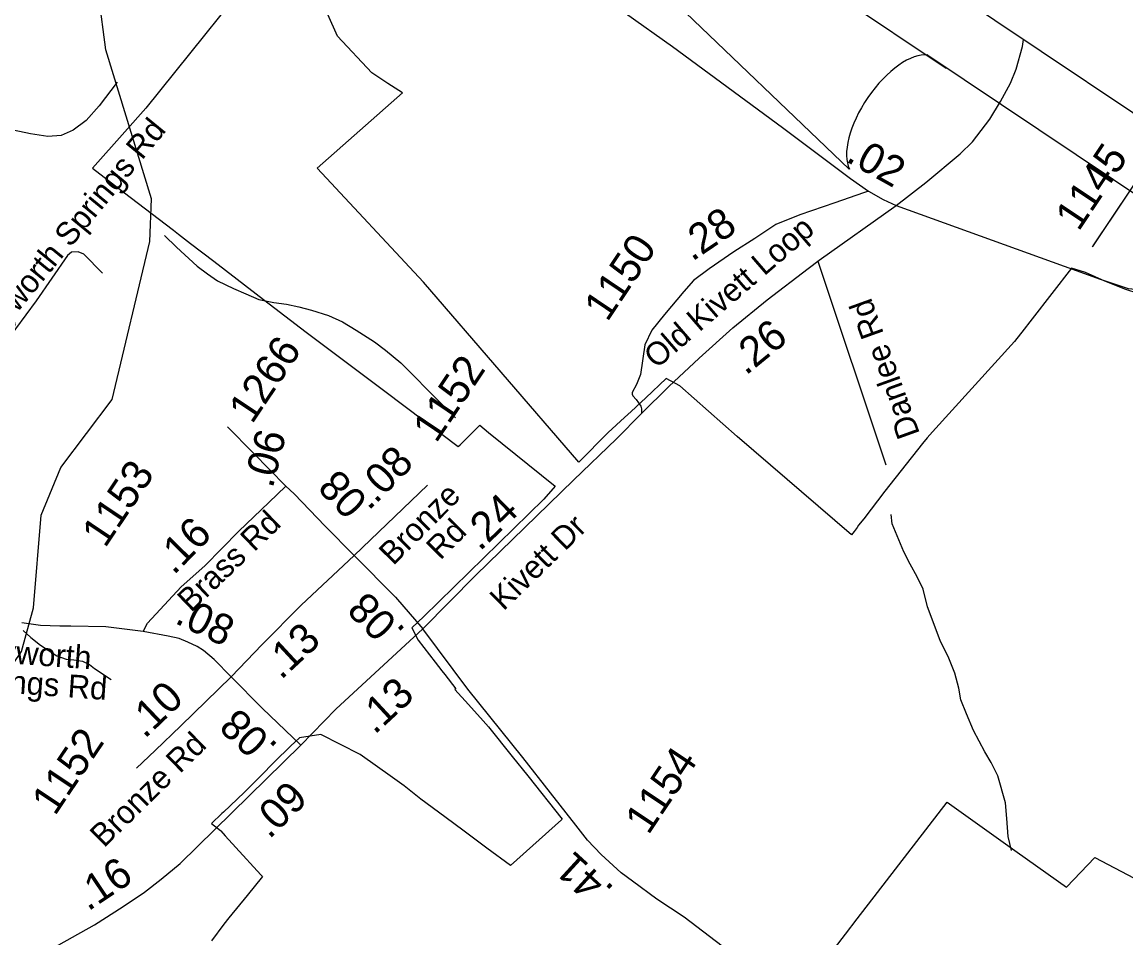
# Model space of a CAD drawing. Extents: x 1715610 to 1720914, y 798298 to 802505.
# Drawn here: x 1715932.8 to 1716031.7, y 799765.7 to 799847.8 of the extents above; entities that cross this region are included whole.
import ezdxf

# ---------------------------------------------------------------- set-up
doc = ezdxf.new("R2010")
doc.units = 0
for name, color, linetype in [('Default', 7, 'Continuous'), ('Prop DSN Text', 7, 'Continuous'), ('Prop North Arrow for Plan Sheets CELL', 7, 'Continuous')]:
    doc.layers.add(name, color=color, linetype=linetype)

msp = doc.modelspace()

# ---------------------------------------------------------------- linework, layer by layer
at = {"layer": 'Default'}
for p, q in [((1716004.107, 799826.397), (1716010.203, 799808.132)), ((1715962.545, 799800.004), (1715969.133, 799806.303))]:
    msp.add_line(p, q, dxfattribs=at)
for points in [[(1715913.865, 799783.456), (1715926.835, 799784.693), (1715929.284, 799786.328), (1715932.753, 799791.412), (1715933.821, 799795.307), (1715934.494, 799803.62), (1715936.271, 799807.905), (1715940.869, 799813.983), (1715944.236, 799828.141), (1715944.399, 799831.987), (1715940.311, 799845.322), (1715939.674, 799850.143), (1715940.195, 799853.75), (1715941.312, 799854.725), (1715943.603, 799854.265), (1715956.425, 799858.901), (1715957.776, 799859.961), (1715959.574, 799863.781), (1715959.922, 799867.267), (1715958.277, 799874.754), (1715959.996, 799882.819), (1715961.653, 799887.001)], [(1715908.697, 799873.648), (1715909.928, 799873.704), (1715920.861, 799873.543), (1715922.854, 799873.496), (1715923.734, 799873.475), (1715928.536, 799873.361), (1715933.353, 799873.131), (1715936.194, 799872.898), (1715938.663, 799872.403), (1715942.933, 799871.337), (1715946.16, 799870.365), (1715954.607, 799867.939), (1715958.8, 799866.637), (1715962.259, 799865.247), (1715963.761, 799864.692), (1715964.59, 799864.335), (1715966.206, 799863.587), (1715970.392, 799860.667), (1715982.657, 799851.643), (1715991.072, 799845.641), (1716000.954, 799838.366), (1716007.032, 799833.787), (1716008.634, 799832.651)], [(1715955.729, 799854.898), (1715943.869, 799840.108), (1715941.991, 799837.985), (1715939.098, 799834.723), (1715941.848, 799832.615), (1715946.356, 799829.159), (1715946.81, 799828.813), (1715947.89, 799827.982), (1715949.986, 799826.376), (1715954.825, 799822.666), (1715954.947, 799822.572), (1715958.261, 799820.03), (1715965.297, 799814.728), (1715968.833, 799812.07), (1715971.886, 799809.769), (1715972.041, 799809.923), (1715973.825, 799811.683), (1715974.597, 799811.042), (1715980.579, 799806.231), (1715979.545, 799805.058), (1715968.808, 799794.539), (1715967.736, 799793.522)], [(1715955.729, 799854.898), (1715943.869, 799840.108), (1715941.991, 799837.985), (1715939.098, 799834.723), (1715941.848, 799832.615), (1715946.356, 799829.159), (1715946.81, 799828.813), (1715947.89, 799827.982), (1715949.986, 799826.376), (1715954.825, 799822.666), (1715954.947, 799822.572), (1715958.261, 799820.03), (1715965.297, 799814.728), (1715968.833, 799812.07), (1715971.886, 799809.769), (1715972.041, 799809.923), (1715973.825, 799811.683), (1715974.597, 799811.042), (1715980.579, 799806.231), (1715979.545, 799805.058), (1715968.808, 799794.539), (1715967.736, 799793.522)], [(1716033.911, 799823.128), (1716031.716, 799823.864), (1716029.825, 799824.606), (1716028.093, 799825.379), (1716026.847, 799825.749), (1716023.302, 799821.215), (1716023.102, 799820.96), (1716022.588, 799820.303), (1716021.723, 799819.2), (1716014.38, 799811.081), (1716013.908, 799810.56), (1716013.473, 799810.036), (1716010.109, 799805.761), (1716008.214, 799803.28), (1716007.746, 799802.71), (1716007.624, 799802.504), (1716007.353, 799802.155), (1716007.121, 799801.856), (1715996.875, 799810.663), (1715991.726, 799815.222), (1715990.512, 799815.861), (1715988.704, 799814.127), (1715987.38, 799812.916), (1715986.79, 799812.375), (1715985.325, 799811.03), (1715982.683, 799808.358), (1715968.76, 799824.515), (1715959.239, 799834.715), (1715966.88, 799841.47), (1715965.579, 799842.321), (1715964.135, 799843.265), (1715961.045, 799846.573), (1715959.438, 799850.204)], [(1716033.911, 799823.128), (1716031.716, 799823.864), (1716029.825, 799824.606), (1716028.093, 799825.379), (1716026.847, 799825.749), (1716023.302, 799821.215), (1716023.102, 799820.96), (1716022.588, 799820.303), (1716021.723, 799819.2), (1716014.38, 799811.081), (1716013.908, 799810.56), (1716013.473, 799810.036), (1716010.109, 799805.761), (1716008.214, 799803.28), (1716007.746, 799802.71), (1716007.624, 799802.504), (1716007.353, 799802.155), (1716007.121, 799801.856), (1715996.875, 799810.663), (1715991.726, 799815.222), (1715990.512, 799815.861), (1715988.704, 799814.127), (1715987.38, 799812.916), (1715986.79, 799812.375), (1715985.325, 799811.03), (1715982.683, 799808.358), (1715968.76, 799824.515), (1715959.239, 799834.715), (1715966.88, 799841.47), (1715965.579, 799842.321), (1715964.135, 799843.265), (1715961.045, 799846.573), (1715959.438, 799850.204)], [(1716011.114, 799831.388), (1716013.774, 799833.456), (1716016.873, 799836.024), (1716017.964, 799837.092), (1716019.534, 799839.126), (1716020.487, 799840.705), (1716021.372, 799842.339), (1716021.885, 799843.606), (1716022.433, 799845.644), (1716022.542, 799846.246)], [(1715941.3, 799842.443), (1715939.695, 799840.324), (1715938.536, 799839.013), (1715937.356, 799838.134), (1715936.288, 799837.651), (1715935.115, 799837.556), (1715933.538, 799837.791), (1715931.419, 799838.238), (1715929.949, 799838.556), (1715928.372, 799838.791), (1715927.298, 799838.839), (1715926.235, 799838.826), (1715925.099, 799838.706), (1715924.057, 799838.26), (1715922.794, 799837.646), (1715920.511, 799836.464), (1715919.063, 799835.501), (1715918.128, 799834.828), (1715916.642, 799833.73), (1715915.513, 799833.079), (1715914.833, 799832.703)], [(1716008.634, 799832.651), (1716008.193, 799832.528), (1716005.615, 799831.608), (1716002.487, 799830.529), (1716000.356, 799829.689), (1715998.467, 799828.426), (1715996.589, 799827.215), (1715994.37, 799825.71), (1715992.976, 799824.669), (1715992.105, 799823.671), (1715990.357, 799821.621), (1715989.236, 799820.196), (1715988.607, 799818.881), (1715988.221, 799816.243), (1715987.849, 799815.343), (1715987.481, 799814.606), (1715987.467, 799814.473), (1715987.514, 799814.312), (1715987.817, 799813.983), (1715988.245, 799813.404), (1715988.306, 799813.158), (1715988.292, 799812.725)], [(1716008.634, 799832.651), (1716009.959, 799831.911), (1716011.114, 799831.388)], [(1715988.292, 799812.725), (1715990.755, 799815.154), (1715993.468, 799817.708), (1715996.485, 799820.404), (1715999.575, 799822.927), (1716003.228, 799825.73), (1716004.219, 799826.492), (1716011.114, 799831.388)], [(1716011.114, 799831.388), (1716029.398, 799824.782), (1716031.908, 799823.95), (1716033.862, 799823.761), (1716035.469, 799823.681), (1716047.398, 799823.718), (1716050.918, 799823.558), (1716053.263, 799823.614), (1716056.007, 799823.848)], [(1715945.548, 799828.684), (1715946.625, 799827.636), (1715948.477, 799825.951), (1715949.42, 799825.25), (1715950.319, 799824.638), (1715951.735, 799823.932), (1715952.83, 799823.451), (1715954.019, 799822.955), (1715955.355, 799822.673), (1715956.476, 799822.54), (1715957.582, 799822.309), (1715958.739, 799821.997), (1715960.266, 799821.533), (1715961.503, 799820.952), (1715962.737, 799820.212), (1715964.379, 799819.145), (1715965.361, 799818.424), (1715966.736, 799817.273), (1715970.364, 799813.637), (1715971.638, 799812.339)], [(1715939.996, 799825.319), (1715938.317, 799827.019), (1715937.804, 799827.218), (1715937.207, 799827.186), (1715936.872, 799826.9), (1715934.066, 799822.823), (1715931.265, 799819.078), (1715930.184, 799817.995), (1715929.118, 799817.053), (1715928.229, 799816.582)], [(1715968.702, 799793.445), (1715973.449, 799798.247), (1715982.221, 799806.744), (1715986.076, 799810.473), (1715988.292, 799812.725)], [(1715956.427, 799806.215), (1715953.511, 799809.194), (1715951.215, 799811.543)], [(1715943.63, 799793.205), (1715944.032, 799793.947), (1715947.058, 799797.185), (1715949.18, 799799.091), (1715952.224, 799802.194), (1715954.905, 799804.754), (1715956.427, 799806.215)], [(1715956.427, 799806.215), (1715957.178, 799805.531), (1715959.959, 799802.642), (1715962.545, 799800.004)], [(1716021.455, 799773.569), (1716021.156, 799774.827), (1716021.041, 799776.434), (1716020.937, 799777.823), (1716020.227, 799780.257), (1716019.626, 799781.459), (1716019.068, 799782.417), (1716018.051, 799784.321), (1716017.431, 799785.804), (1716016.913, 799787.053), (1716016.744, 799788.116), (1716016.396, 799789.46), (1716015.834, 799790.797), (1716015.067, 799792.373), (1716013.931, 799795.414), (1716013.537, 799796.998), (1716013.018, 799798.091), (1716012.367, 799799.219), (1716011.812, 799800.337), (1716010.78, 799802.836), (1716010.679, 799803.692)], [(1715951.53, 799789.119), (1715954.307, 799792.031), (1715957.812, 799795.551), (1715962.545, 799800.004)], [(1715962.545, 799800.004), (1715966.263, 799796.257), (1715968.702, 799793.445)], [(1715943.63, 799793.205), (1715940.312, 799793.621), (1715937.148, 799793.669), (1715936.184, 799793.668), (1715934.449, 799793.742), (1715932.777, 799793.98)], [(1715932.902, 799793.276), (1715933.583, 799792.654), (1715934.431, 799791.968), (1715935.894, 799791.022), (1715936.734, 799790.711), (1715937.435, 799790.656), (1715938.204, 799790.548), (1715938.828, 799790.228), (1715939.271, 799789.872), (1715940.768, 799788.902)], [(1715951.53, 799789.119), (1715950.017, 799790.679), (1715949.053, 799791.497), (1715948.494, 799791.835), (1715947.659, 799792.24), (1715946.883, 799792.556), (1715945.897, 799792.788), (1715943.63, 799793.205)], [(1715967.736, 799793.522), (1715968.276, 799792.425), (1715969.82, 799790.439), (1715970.411, 799789.68), (1715970.668, 799789.351), (1715971.677, 799788.051), (1715971.572, 799787.984), (1715972.793, 799786.65), (1715974.128, 799785.187), (1715974.606, 799784.661), (1715976.726, 799781.999), (1715978.11, 799780.261), (1715981.207, 799776.373), (1715981.129, 799776.304), (1715976.57, 799772.217), (1715974.449, 799773.784), (1715972.407, 799775.291), (1715970.669, 799776.572), (1715968.515, 799778.164), (1715967.022, 799779.37), (1715965.974, 799780.117), (1715963.105, 799782.162), (1715959.567, 799783.961), (1715957.65, 799783.653), (1715956.839, 799782.92), (1715955.419, 799781.499), (1715954.145, 799780.212), (1715952.703, 799778.76), (1715950.834, 799777.004), (1715950.694, 799776.872), (1715949.754, 799775.98), (1715950.574, 799775.352), (1715950.606, 799775.318), (1715950.989, 799774.888), (1715951.952, 799773.835), (1715954.182, 799771.394), (1715954.331, 799771.231), (1715952.96, 799769.539), (1715951.326, 799767.521), (1715950.864, 799766.95), (1715949.77, 799765.474)], [(1715967.736, 799793.522), (1715968.276, 799792.425), (1715969.82, 799790.439), (1715970.411, 799789.68), (1715970.668, 799789.351), (1715971.677, 799788.051), (1715971.572, 799787.984), (1715972.793, 799786.65), (1715974.128, 799785.187), (1715974.606, 799784.661), (1715976.726, 799781.999), (1715978.11, 799780.261), (1715981.207, 799776.373), (1715981.129, 799776.304), (1715976.57, 799772.217), (1715974.449, 799773.784), (1715972.407, 799775.291), (1715970.669, 799776.572), (1715968.515, 799778.164), (1715967.022, 799779.37), (1715965.974, 799780.117), (1715963.105, 799782.162), (1715959.567, 799783.961), (1715957.65, 799783.653), (1715956.839, 799782.92), (1715955.419, 799781.499), (1715954.145, 799780.212), (1715952.703, 799778.76), (1715950.834, 799777.004), (1715950.694, 799776.872), (1715949.754, 799775.98), (1715950.574, 799775.352), (1715950.606, 799775.318), (1715950.989, 799774.888), (1715951.952, 799773.835), (1715954.182, 799771.394), (1715954.331, 799771.231), (1715952.96, 799769.539), (1715951.326, 799767.521), (1715950.864, 799766.95), (1715949.77, 799765.474)], [(1715957.762, 799783.015), (1715960.904, 799786.222), (1715968.702, 799793.445)], [(1715999.432, 799761.987), (1715992.134, 799767.58), (1715989.691, 799769.214), (1715987.49, 799770.8), (1715986.473, 799771.562), (1715984.679, 799773.204), (1715983.47, 799774.479), (1715982.404, 799775.822), (1715980.138, 799778.724), (1715977.67, 799781.9), (1715972.737, 799788.033), (1715968.702, 799793.445)], [(1715943.038, 799780.956), (1715944.718, 799782.532), (1715947.014, 799784.736), (1715951.53, 799789.119)], [(1715957.762, 799783.015), (1715954.302, 799786.31), (1715951.53, 799789.119)], [(1715935.353, 799764.685), (1715939.274, 799766.904), (1715941.846, 799768.533), (1715943.771, 799769.821), (1715945.257, 799770.984), (1715946.967, 799772.383), (1715957.762, 799783.015)], [(1716002.347, 799760.535), (1716006.596, 799766.073), (1716007.642, 799767.434), (1716009.45, 799769.784), (1716015.691, 799777.891)], [(1716002.347, 799760.535), (1716006.596, 799766.073), (1716007.642, 799767.434), (1716009.45, 799769.784), (1716015.691, 799777.891)], [(1716015.691, 799777.891), (1716021.962, 799773.422), (1716026.399, 799770.262)], [(1716015.691, 799777.891), (1716021.962, 799773.422), (1716026.399, 799770.262)], [(1716026.399, 799770.262), (1716028.92, 799772.926), (1716040.648, 799766.765)], [(1716026.399, 799770.262), (1716028.92, 799772.926), (1716040.648, 799766.765)]]:
    msp.add_lwpolyline(points, dxfattribs=at)
at = {"layer": 'Prop DSN Text'}
msp.add_lwpolyline([(1715972.317, 799278.019), (1716250.513, 799693.662), (1715888.228, 799936.145), (1715610.032, 799520.501)], close=True, dxfattribs=at)
at = {"layer": 'Prop North Arrow for Plan Sheets CELL'}
for p, q in [((1716006.917, 799834.63), (1715955.981, 799883.523)), ((1715956.023, 799883.585), (1716015.608, 799843.704)), ((1716046.522, 799823.013), (1716013.863, 799844.872)), ((1716015.608, 799843.704), (1716013.925, 799844.83)), ((1716028.767, 799827.767), (1716035.442, 799837.739)), ((1716031.687, 799832.13), (1716028.725, 799827.705)), ((1716028.725, 799827.705), (1716028.683, 799827.642))]:
    msp.add_line(p, q, dxfattribs=at)
msp.add_ellipse((1716010.986, 799839.373), major_axis=(3.567, 5.248), ratio=0.461098, start_param=0.216388, end_param=2.908219, dxfattribs=at)

# ---------------------------------------------------------------- texts
at = {"layer": 'Default'}
for s, height, rotation, p in [('Hayworth Springs Rd', 2.06625, 50.67435, (1715929.236, 799817.92)), ('.02', 2.7188, 330.80515, (1716006.518, 799835.387)), ('1145', 2.7188, 56.20506, (1716027.474, 799828.985)), ('.28', 2.7188, 34.12786, (1715992.838, 799826.314)), ('Old Kivett Loop', 2.06625, 40.81056, (1715989.645, 799816.678)), ('1150', 2.7188, 56.20506, (1715985.241, 799820.877)), ('Danlee Rd', 2.0663, 109.85489, (1716013.276, 799810.925)), ('.26', 2.7188, 39.23081, (1715997.65, 799816.09)), ('1266', 2.7188, 56.20506, (1715953.403, 799811.716)), ('1152', 2.7188, 56.20506, (1715969.904, 799810.009)), ('.06', 2.7188, 75.87353, (1715955.25, 799805.963)), ('.08', 2.7188, 45.61569, (1715964.485, 799804.577)), ('1153', 2.7188, 56.20506, (1715940.236, 799800.609)), ('.08', 2.7188, 133.90369, (1715964.605, 799804.258)), ('Bronze', 2.0663, 45.12863, (1715966.049, 799799.031)), ('.24', 2.7188, 44.08762, (1715973.821, 799800.323)), ('Brass Rd', 2.0663, 43.88272, (1715947.936, 799794.843)), ('.16', 2.7188, 45.54997, (1715946.39, 799798.188)), (' Rd', 2.0663, 45.12863, (1715969.737, 799798.974)), ('Kivett Dr', 2.0663, 44.36084, (1715975.946, 799794.976)), ('.08', 2.7188, 334.16258, (1715946.373, 799793.996)), ('.08', 2.7188, 134.78275, (1715967.249, 799793.334)), ('.13', 2.7188, 42.84644, (1715955.992, 799788.797)), ('Hayworth ', 2.0663, 355.96648, (1715927.299, 799790.633)), ('Springs Rd', 2.0663, 355.96648, (1715926.715, 799788.014)), ('.13', 2.7188, 42.80469, (1715964.385, 799783.887)), ('.10', 2.7188, 43.83066, (1715943.78, 799783.516)), ('.08', 2.7188, 136.40023, (1715955.822, 799782.985)), ('1152', 2.7188, 56.20506, (1715935.739, 799776.593)), ('Bronze Rd', 2.0663, 44.4168, (1715940.126, 799773.741)), ('1154', 2.7188, 56.20506, (1715988.919, 799774.886)), ('.09', 2.7188, 44.56256, (1715954.945, 799774.516)), ('.16', 2.7188, 33.78891, (1715938.704, 799768.066)), ('.41', 2.7188, 137.51328, (1715985.947, 799770.202))]:
    msp.add_text(s, height=height, rotation=rotation, dxfattribs=at).set_placement(p)

doc.saveas('drawing.dxf')
